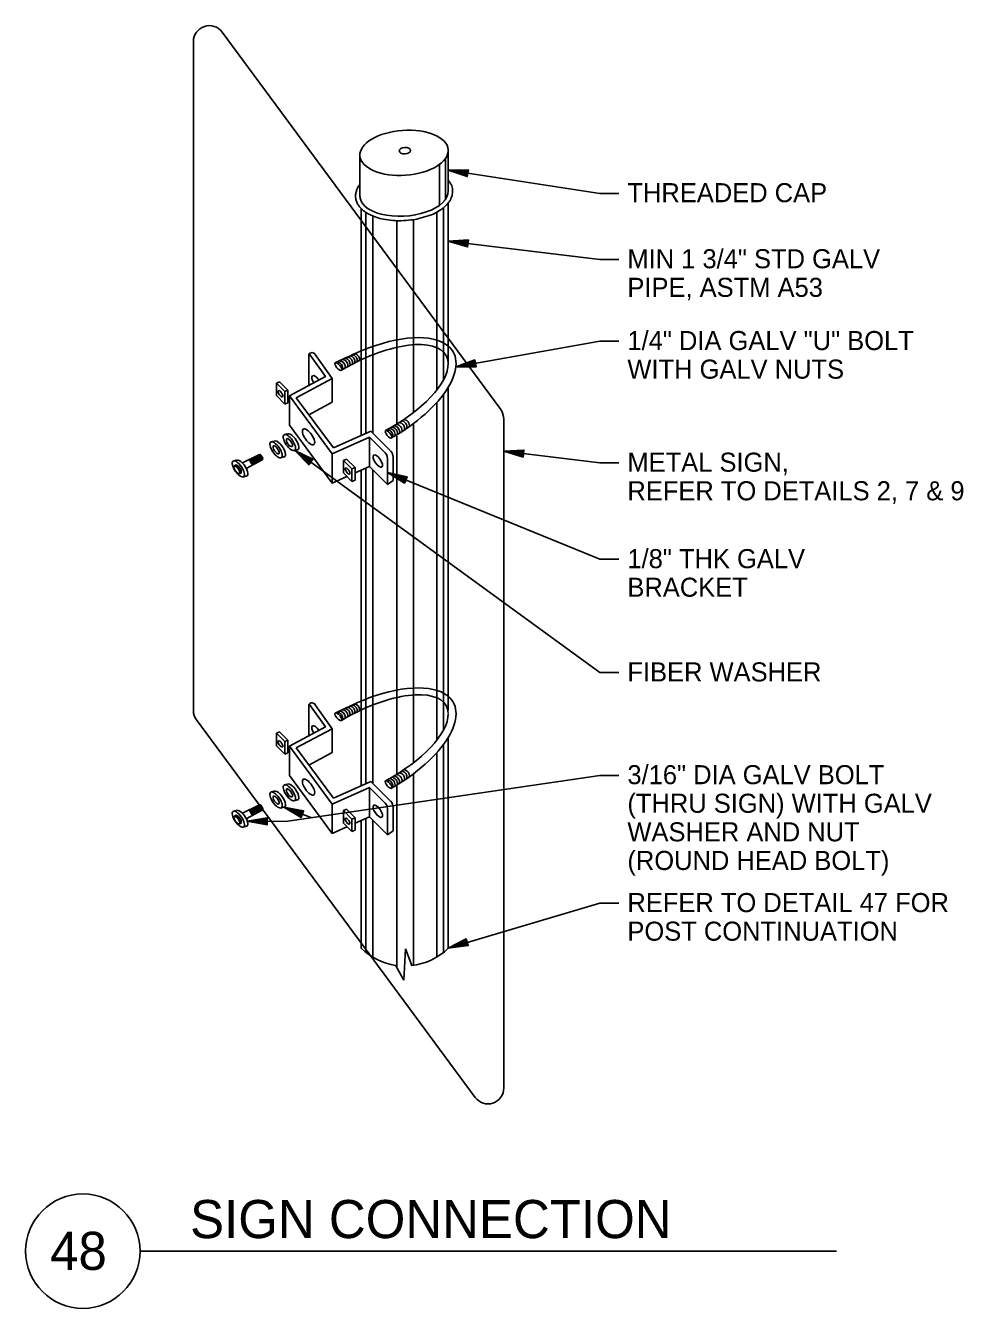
# Model space of a CAD drawing. Extents: x -121875 to -117742, y -103854 to -101122.
# Drawn here: x -120027.3 to -119732.2, y -101990.3 to -101586.5 of the extents above; entities that cross this region are included whole.
import ezdxf

# ---------------------------------------------------------------- set-up
doc = ezdxf.new("R2010")
doc.units = 0
doc.layers.add('22', color=7, linetype='Continuous')

msp = doc.modelspace()

# ---------------------------------------------------------------- linework, layer by layer
at = {"layer": '22'}
for p, q in [((-119877.8, -101707.38), (-119965.5, -101588.57)), ((-119974.52, -101591.53), (-119974.52, -101802.11)), ((-119922.11, -101640.42), (-119922.11, -101627.55)), ((-119894.32, -101638.44), (-119894.32, -101625.57)), ((-119897.12, -101643.11), (-119897.12, -101630.24)), ((-119895.14, -101641.15), (-119895.14, -101628.28)), ((-119894.32, -101693.31), (-119894.32, -101642.33)), ((-119921.71, -101715.56), (-119921.71, -101644.13)), ((-119920.23, -101714.9), (-119920.23, -101645.32)), ((-119918.08, -101714.77), (-119918.08, -101646.43)), ((-119905.21, -101708.26), (-119905.21, -101647.57)), ((-119897.95, -101701.23), (-119897.95, -101645.24)), ((-119895.8, -101698.01), (-119895.8, -101643.82)), ((-119910.49, -101711.63), (-119910.49, -101647.9)), ((-119938.2, -101689.99), (-119938.2, -101699.84)), ((-119930.86, -101697.58), (-119936.17, -101690.05)), ((-119926.19, -101690.93), (-119929.87, -101692.68)), ((-119947.43, -101698.62), (-119948.42, -101699.04)), ((-119945.79, -101701.67), (-119948.42, -101699.04)), ((-119948.42, -101699.04), (-119948.42, -101702.94)), ((-119944.8, -101701.25), (-119947.43, -101698.62)), ((-119942.15, -101703.65), (-119930.86, -101697.58)), ((-119930.86, -101697.58), (-119930.86, -101705.06)), ((-119948.42, -101702.99), (-119945.79, -101705.63)), ((-119944.8, -101701.25), (-119945.79, -101701.67)), ((-119945.79, -101705.63), (-119945.79, -101701.67)), ((-119944.8, -101705.21), (-119944.8, -101701.25)), ((-119944.27, -101703.08), (-119944.27, -101712.32)), ((-119930.48, -101719.47), (-119942.15, -101703.65)), ((-119895.8, -101808.36), (-119895.8, -101702.53)), ((-119894.32, -101802.01), (-119894.32, -101700.33)), ((-119944.8, -101705.21), (-119945.79, -101705.63)), ((-119897.95, -101811.47), (-119897.95, -101705.14)), ((-119905.21, -101818.24), (-119905.21, -101712.13)), ((-119876.83, -101920.92), (-119876.83, -101710.35)), ((-119944.98, -101715.04), (-119946.02, -101715.33)), ((-119918.66, -101714.2), (-119930.48, -101719.47)), ((-119919.13, -101716.08), (-119919.13, -101725.31)), ((-119912.44, -101720.41), (-119918.66, -101714.2)), ((-119910.49, -101822.23), (-119910.49, -101715.76)), ((-119949.17, -101717.31), (-119950.21, -101717.59)), ((-119941.59, -101719.95), (-119942.63, -101720.23)), ((-119961.04, -101723.34), (-119962.07, -101723.62)), ((-119953.93, -101721.64), (-119959.07, -101724.19)), ((-119952.9, -101723.25), (-119957.89, -101725.93)), ((-119955.63, -101724.7), (-119956.94, -101723.1)), ((-119956.94, -101723.1), (-119955.95, -101724.89)), ((-119955.35, -101724.56), (-119956.62, -101722.96)), ((-119956.62, -101722.96), (-119955.63, -101724.7)), ((-119955.01, -101724.37), (-119956.24, -101722.77)), ((-119956.24, -101722.77), (-119955.35, -101724.56)), ((-119954.68, -101724.23), (-119955.91, -101722.68)), ((-119955.91, -101722.68), (-119955.01, -101724.37)), ((-119954.4, -101724.04), (-119955.63, -101722.54)), ((-119955.63, -101722.54), (-119954.68, -101724.23)), ((-119954.07, -101723.85), (-119955.39, -101722.4)), ((-119955.39, -101722.4), (-119954.4, -101724.04)), ((-119953.69, -101723.67), (-119955.06, -101722.21)), ((-119955.06, -101722.21), (-119954.07, -101723.85)), ((-119953.32, -101723.48), (-119954.68, -101722.07)), ((-119954.68, -101722.07), (-119953.69, -101723.67)), ((-119952.99, -101723.34), (-119954.36, -101721.93)), ((-119954.36, -101721.93), (-119953.32, -101723.48)), ((-119952.7, -101723.1), (-119954.07, -101721.73)), ((-119954.07, -101721.73), (-119952.99, -101723.34)), ((-119952.7, -101722.72), (-119953.79, -101721.55)), ((-119953.79, -101721.55), (-119952.7, -101723.1)), ((-119952.65, -101722.72), (-119953.32, -101721.69)), ((-119945.79, -101722.21), (-119946.82, -101722.49)), ((-119930.81, -101721.31), (-119930.81, -101730.54)), ((-119926.29, -101722.96), (-119927.28, -101723.39)), ((-119924.64, -101726.02), (-119927.28, -101723.39)), ((-119927.28, -101723.39), (-119927.28, -101727.29)), ((-119923.65, -101725.6), (-119926.29, -101722.96)), ((-119913.48, -101723.39), (-119913.48, -101730.96)), ((-119911.68, -101722.4), (-119911.68, -101729.74)), ((-119961.56, -101725.08), (-119961.09, -101724.8)), ((-119960.8, -101725.5), (-119960.34, -101725.22)), ((-119960.01, -101726.68), (-119959.53, -101726.39)), ((-119959.96, -101727.53), (-119959.49, -101727.25)), ((-119957.65, -101728.24), (-119958.69, -101728.52)), ((-119927.28, -101727.34), (-119924.64, -101729.97)), ((-119923.65, -101725.6), (-119924.64, -101726.02)), ((-119924.64, -101729.97), (-119924.64, -101726.02)), ((-119923.65, -101729.55), (-119923.65, -101725.6)), ((-119921.71, -101825.75), (-119921.71, -101726.42)), ((-119920.23, -101825.14), (-119920.23, -101726.01)), ((-119918.08, -101825.01), (-119918.08, -101726.3)), ((-119923.65, -101729.55), (-119924.64, -101729.97)), ((-119913.48, -101730.96), (-119911.68, -101729.74)), ((-119938.2, -101800.23), (-119938.2, -101810.08)), ((-119930.86, -101807.82), (-119936.17, -101800.29)), ((-119926.19, -101801.17), (-119929.87, -101802.92)), ((-119973.55, -101805.08), (-119885.85, -101923.89)), ((-119947.43, -101808.86), (-119948.42, -101809.28)), ((-119945.79, -101811.91), (-119948.42, -101809.28)), ((-119948.42, -101809.28), (-119948.42, -101813.18)), ((-119944.8, -101811.49), (-119947.43, -101808.86)), ((-119942.15, -101813.89), (-119930.86, -101807.82)), ((-119930.86, -101807.82), (-119930.86, -101815.3)), ((-119948.42, -101813.23), (-119945.79, -101815.87)), ((-119944.8, -101811.49), (-119945.79, -101811.91)), ((-119945.79, -101815.87), (-119945.79, -101811.91)), ((-119944.8, -101815.44), (-119944.8, -101811.49)), ((-119895.8, -101878.23), (-119895.8, -101812.77)), ((-119894.32, -101876.91), (-119894.32, -101810.57)), ((-119944.8, -101815.44), (-119945.79, -101815.87)), ((-119944.27, -101813.32), (-119944.27, -101822.55)), ((-119930.48, -101829.71), (-119942.15, -101813.89)), ((-119897.95, -101879.73), (-119897.95, -101815.38)), ((-119944.98, -101825.28), (-119946.02, -101825.57)), ((-119918.66, -101824.44), (-119930.48, -101829.71)), ((-119912.44, -101830.65), (-119918.66, -101824.44)), ((-119905.21, -101882.32), (-119905.21, -101821.95)), ((-119949.17, -101827.54), (-119950.21, -101827.83)), ((-119919.13, -101826.32), (-119919.13, -101835.55)), ((-119910.49, -101883.04), (-119910.49, -101825.5)), ((-119953.93, -101831.88), (-119959.07, -101834.42)), ((-119952.9, -101833.49), (-119957.89, -101836.17)), ((-119955.63, -101834.94), (-119956.94, -101833.34)), ((-119956.94, -101833.34), (-119955.95, -101835.13)), ((-119955.35, -101834.8), (-119956.62, -101833.2)), ((-119956.62, -101833.2), (-119955.63, -101834.94)), ((-119955.01, -101834.61), (-119956.24, -101833.01)), ((-119956.24, -101833.01), (-119955.35, -101834.8)), ((-119954.68, -101834.47), (-119955.91, -101832.92)), ((-119955.91, -101832.92), (-119955.01, -101834.61)), ((-119954.4, -101834.28), (-119955.63, -101832.78)), ((-119955.63, -101832.78), (-119954.68, -101834.47)), ((-119954.07, -101834.09), (-119955.39, -101832.64)), ((-119955.39, -101832.64), (-119954.4, -101834.28)), ((-119953.69, -101833.91), (-119955.06, -101832.45)), ((-119955.06, -101832.45), (-119954.07, -101834.09)), ((-119953.32, -101833.72), (-119954.68, -101832.3)), ((-119954.68, -101832.3), (-119953.69, -101833.91)), ((-119952.99, -101833.58), (-119954.36, -101832.17)), ((-119954.36, -101832.17), (-119953.32, -101833.72)), ((-119952.7, -101833.34), (-119954.07, -101831.97)), ((-119954.07, -101831.97), (-119952.99, -101833.58)), ((-119952.7, -101832.96), (-119953.79, -101831.79)), ((-119953.79, -101831.79), (-119952.7, -101833.34)), ((-119952.65, -101832.96), (-119953.32, -101831.93)), ((-119945.79, -101832.45), (-119946.82, -101832.73)), ((-119941.59, -101830.18), (-119942.63, -101830.47)), ((-119930.81, -101831.55), (-119930.81, -101840.78)), ((-119926.29, -101833.2), (-119927.28, -101833.63)), ((-119923.65, -101835.84), (-119926.29, -101833.2)), ((-119911.68, -101832.64), (-119911.68, -101839.98)), ((-119961.04, -101833.58), (-119962.07, -101833.86)), ((-119961.56, -101835.32), (-119961.09, -101835.04)), ((-119960.8, -101835.74), (-119960.34, -101835.46)), ((-119960.01, -101836.92), (-119959.53, -101836.63)), ((-119959.96, -101837.77), (-119959.49, -101837.49)), ((-119924.64, -101836.26), (-119927.28, -101833.63)), ((-119927.28, -101833.63), (-119927.28, -101837.53)), ((-119923.65, -101835.84), (-119924.64, -101836.26)), ((-119924.64, -101840.21), (-119924.64, -101836.26)), ((-119923.65, -101839.79), (-119923.65, -101835.84)), ((-119921.71, -101876.91), (-119921.71, -101836.71)), ((-119920.23, -101878.23), (-119920.23, -101836.05)), ((-119918.08, -101879.73), (-119918.08, -101836.6)), ((-119913.48, -101833.63), (-119913.48, -101841.2)), ((-119957.65, -101838.48), (-119958.69, -101838.76)), ((-119927.28, -101837.58), (-119924.64, -101840.21)), ((-119923.65, -101839.79), (-119924.64, -101840.21)), ((-119913.48, -101841.2), (-119911.68, -101839.98)), ((-119907.76, -101877.08), (-119908.25, -101886.98)), ((-119905.79, -101882.4), (-119907.76, -101877.08)), ((-119908.25, -101886.98), (-119910.91, -101882.31)), ((-119772.06, -101972.28), (-119991.33, -101972.28))]:
    msp.add_line(p, q, dxfattribs=at)
for points in [[(-119887.97, -101631.87), (-119888.31, -101634.04), (-119894.32, -101632), (-119887.97, -101631.87), (-119888.44, -101632.91), (-119888.46, -101633.71), (-119892.98, -101632.16), (-119888.2, -101632.04), (-119888.64, -101632.88), (-119888.71, -101633.37), (-119891.84, -101632.33), (-119888.64, -101632.27), (-119888.84, -101633.2), (-119890.71, -101632.56), (-119888.89, -101632.54), (-119889.1, -101632.96), (-119889.72, -101632.71), (-119888.14, -101632.96)], [(-119840.59, -101639.32), (-119846.59, -101639.32), (-119894.32, -101632)], [(-119887.98, -101653.99), (-119888.25, -101656.17), (-119894.32, -101654.33), (-119887.98, -101653.99), (-119888.41, -101655.04), (-119888.41, -101655.85), (-119892.97, -101654.44), (-119888.2, -101654.16), (-119888.61, -101655.02), (-119888.67, -101655.51), (-119891.83, -101654.58), (-119888.64, -101654.41), (-119888.8, -101655.35), (-119890.7, -101654.76), (-119888.87, -101654.68), (-119889.07, -101655.11), (-119889.7, -101654.88), (-119888.11, -101655.08)], [(-119840.59, -101660.12), (-119846.59, -101660.12), (-119894.32, -101654.33)], [(-119840.59, -101685.86), (-119846.59, -101685.86), (-119891.91, -101693.94)], [(-119914.19, -101721.03), (-119919.13, -101716.08), (-119930.81, -101721.31), (-119944.27, -101703.08), (-119932.98, -101697.01), (-119937.97, -101689.99)], [(-119885.95, -101691.77), (-119885.57, -101693.94), (-119891.91, -101693.94), (-119885.95, -101691.77), (-119886.05, -101692.91), (-119885.82, -101693.68), (-119890.59, -101693.65), (-119886.11, -101692), (-119886.25, -101692.94), (-119886.16, -101693.43), (-119889.46, -101693.45), (-119886.45, -101692.37), (-119886.34, -101693.31), (-119888.32, -101693.31), (-119886.6, -101692.7), (-119886.67, -101693.17), (-119887.33, -101693.13), (-119885.76, -101692.86)], [(-119938.15, -101709.07), (-119930.86, -101705.06)], [(-119926.19, -101728.47), (-119930.81, -101730.54), (-119944.27, -101712.32)], [(-119840.59, -101790.16), (-119846.59, -101790.16), (-119942.64, -101720.23)], [(-119936.93, -101723), (-119938.22, -101724.78), (-119942.64, -101720.23), (-119936.93, -101723), (-119937.81, -101723.71), (-119938.2, -101724.42), (-119941.51, -101720.98), (-119937.21, -101723.04), (-119937.98, -101723.59), (-119938.27, -101724), (-119940.58, -101721.65), (-119937.71, -101723.05), (-119938.3, -101723.79), (-119939.68, -101722.36), (-119938.04, -101723.18), (-119938.43, -101723.45), (-119938.87, -101722.95), (-119937.57, -101723.89)], [(-119870.49, -101720.14), (-119870.75, -101722.32), (-119876.83, -101720.48), (-119870.49, -101720.14), (-119870.92, -101721.19), (-119870.92, -101722), (-119875.48, -101720.59), (-119870.71, -101720.31), (-119871.12, -101721.17), (-119871.18, -101721.67), (-119874.34, -101720.73), (-119871.14, -101720.56), (-119871.31, -101721.5), (-119873.2, -101720.92), (-119871.38, -101720.84), (-119871.58, -101721.27), (-119872.21, -101721.04), (-119870.62, -101721.23)], [(-119840.59, -101724.15), (-119846.59, -101724.15), (-119876.83, -101720.48)], [(-119960.24, -101726.25), (-119960.8, -101725.5), (-119961.56, -101725.08), (-119961.84, -101725.55), (-119961.47, -101726.44), (-119961, -101727.06), (-119960.48, -101727.53), (-119959.96, -101727.53), (-119960.01, -101726.68), (-119960.29, -101726.21)], [(-119959.77, -101725.97), (-119960.34, -101725.22), (-119961.09, -101724.8), (-119961.09, -101724.84)], [(-119959.53, -101727.25), (-119959.49, -101727.25), (-119959.53, -101726.39), (-119959.81, -101725.93)], [(-119913.48, -101730.96), (-119919.13, -101725.31), (-119923.65, -101727.34)], [(-119840.59, -101754.51), (-119846.59, -101754.51), (-119913.48, -101727.17)], [(-119907.27, -101728.5), (-119908.1, -101730.54), (-119913.48, -101727.17), (-119907.27, -101728.5), (-119907.96, -101729.4), (-119908.17, -101730.18), (-119912.21, -101727.63), (-119907.53, -101728.61), (-119908.15, -101729.33), (-119908.34, -101729.79), (-119911.14, -101728.06), (-119908.02, -101728.74), (-119908.42, -101729.6), (-119910.1, -101728.54), (-119908.31, -101728.94), (-119908.62, -101729.3), (-119909.17, -101728.92), (-119907.69, -101729.52)], [(-119914.19, -101831.27), (-119919.13, -101826.32), (-119930.81, -101831.55), (-119944.27, -101813.32), (-119932.98, -101807.25), (-119937.97, -101800.23)], [(-119938.15, -101819.31), (-119930.86, -101815.3)], [(-119840.59, -101822.51), (-119846.59, -101822.51), (-119945.59, -101837.08)], [(-119926.19, -101838.71), (-119930.81, -101840.78), (-119944.27, -101822.55)], [(-119937.21, -101835.84), (-119946.09, -101832.54)], [(-119939.85, -101833.66), (-119940.61, -101835.73), (-119946.09, -101832.54), (-119939.85, -101833.66), (-119940.51, -101834.59), (-119940.69, -101835.38), (-119944.81, -101832.95), (-119940.11, -101833.78), (-119940.7, -101834.52), (-119940.87, -101834.99), (-119943.73, -101833.35), (-119940.58, -101833.93), (-119940.96, -101834.8), (-119942.67, -101833.8), (-119940.88, -101834.14), (-119941.17, -101834.51), (-119941.73, -101834.14), (-119940.23, -101834.7)], [(-119960.24, -101836.49), (-119960.8, -101835.74), (-119961.56, -101835.32), (-119961.84, -101835.79), (-119961.47, -101836.68), (-119961, -101837.3), (-119960.48, -101837.77), (-119959.96, -101837.77), (-119960.01, -101836.92), (-119960.29, -101836.45)], [(-119959.77, -101836.21), (-119960.34, -101835.46), (-119961.09, -101835.04), (-119961.09, -101835.08)], [(-119959.53, -101837.49), (-119959.49, -101837.49), (-119959.53, -101836.63), (-119959.81, -101836.17)], [(-119951.3, -101835.9), (-119951.32, -101838.1), (-119957.56, -101836.94), (-119951.3, -101835.9), (-119951.61, -101837), (-119951.51, -101837.8), (-119956.2, -101836.9), (-119951.5, -101836.1), (-119951.81, -101837), (-119951.81, -101837.5), (-119955.05, -101836.91), (-119951.9, -101836.4), (-119951.96, -101837.35), (-119953.91, -101836.98), (-119952.1, -101836.69), (-119952.26, -101837.14), (-119952.91, -101836.98), (-119951.31, -101837)], [(-119945.59, -101837.08), (-119957.56, -101836.94)], [(-119913.48, -101841.2), (-119919.13, -101835.55), (-119923.65, -101837.58)], [(-119840.59, -101862.78), (-119846.59, -101862.78), (-119894.32, -101876.91)], [(-119888.68, -101874.01), (-119888.02, -101876.11), (-119894.32, -101876.91), (-119888.68, -101874.01), (-119888.64, -101875.14), (-119888.3, -101875.88), (-119893.04, -101876.46), (-119888.81, -101874.26), (-119888.83, -101875.2), (-119888.68, -101875.68), (-119891.95, -101876.12), (-119889.1, -101874.66), (-119888.87, -101875.58), (-119890.83, -101875.83), (-119889.2, -101875.01), (-119889.21, -101875.48), (-119889.88, -101875.53), (-119888.35, -101875.06)]]:
    msp.add_lwpolyline(points, dxfattribs=at)
msp.add_circle((-120009.33, -101972.28), 18, dxfattribs=at)
for centre, radius, start, end in [((-119969.52, -101591.53), 5, 36.4317, 180), ((-119937.2, -101690.66), 1.2, 30.9874, 146.3482), ((-119938.06, -101690.16), 0.217, 77.4712, 130.6013), ((-119928.68, -101693.94), 1.92, 348.2285, 85.9146), ((-119927.83, -101693.52), 1.92, 348.2285, 85.9146), ((-119927.16, -101693.16), 1.98, 353.3183, 77.9923), ((-119926.41, -101692.78), 1.98, 353.3183, 77.9923), ((-119925.66, -101692.36), 1.98, 353.3183, 77.9923), ((-119924.9, -101692.03), 1.98, 353.3183, 77.9923), ((-119924.2, -101691.7), 1.98, 353.3183, 77.9923), ((-119929.43, -101694.32), 1.92, 348.2285, 85.9146), ((-119881.83, -101710.35), 5, 0, 36.4317), ((-119910.78, -101713.95), 1.92, 348.2285, 85.9146), ((-119909.98, -101713.39), 1.92, 348.2285, 85.9146), ((-119909.23, -101712.87), 1.92, 348.2285, 85.9146), ((-119908.48, -101712.4), 1.92, 348.2285, 85.9146), ((-119913.66, -101715.65), 1.92, 348.2285, 85.9146), ((-119912.95, -101715.23), 1.92, 348.2285, 85.9146), ((-119912.24, -101714.8), 1.92, 348.2285, 85.9146), ((-119911.58, -101714.38), 1.92, 348.2285, 85.9146), ((-119914.26, -101722.25), 2.58, 356.6267, 44.9178), ((-119953.67, -101722.1), 0.549, 50.7562, 120.4157), ((-119953.03, -101722.87), 0.402, 290.556, 20.556), ((-119916, -101722.86), 2.58, 348.5235, 44.9178), ((-119937.2, -101800.9), 1.2, 30.9874, 146.3482), ((-119938.06, -101800.4), 0.217, 77.4712, 130.6013), ((-119926.41, -101803.02), 1.98, 353.3183, 77.9923), ((-119925.66, -101802.6), 1.98, 353.3183, 77.9923), ((-119924.9, -101802.27), 1.98, 353.3183, 77.9923), ((-119924.2, -101801.94), 1.98, 353.3183, 77.9923), ((-119969.52, -101802.11), 5, 180, 216.4317), ((-119929.43, -101804.56), 1.92, 348.2285, 85.9146), ((-119928.68, -101804.18), 1.92, 348.2285, 85.9146), ((-119927.83, -101803.76), 1.92, 348.2285, 85.9146), ((-119927.16, -101803.4), 1.98, 353.3183, 77.9923), ((-119909.23, -101823.11), 1.92, 348.2285, 85.9146), ((-119908.48, -101822.64), 1.92, 348.2285, 85.9146), ((-119913.66, -101825.89), 1.92, 348.2285, 85.9146), ((-119912.95, -101825.47), 1.92, 348.2285, 85.9146), ((-119912.24, -101825.04), 1.92, 348.2285, 85.9146), ((-119911.58, -101824.62), 1.92, 348.2285, 85.9146), ((-119910.78, -101824.19), 1.92, 348.2285, 85.9146), ((-119909.98, -101823.63), 1.92, 348.2285, 85.9146), ((-119953.67, -101832.34), 0.549, 50.7562, 120.4157), ((-119953.03, -101833.11), 0.402, 290.556, 20.556), ((-119916, -101833.1), 2.58, 348.5235, 44.9178), ((-119914.26, -101832.49), 2.58, 356.6267, 44.9178), ((-119908.02, -101863), 19.52, 225.4381, 261.6907), ((-119908.02, -101863), 19.52, 276.1221, 314.5619), ((-119881.83, -101920.92), 5, 216.4317, 0)]:
    msp.add_arc(centre, radius, start, end, dxfattribs=at)
for centre, major_axis, ratio in [((-119908.22, -101626.56), (-13.9, -0.99), 0.50721), ((-119907.96, -101625.88), (-1.77, -0.06), 0.577116), ((-119928.9, -101693.84), (-0.97, 1.15), 0.383233), ((-119928.9, -101693.84), (-0.97, 1.15), 0.383233), ((-119947.14, -101702.38), (0.646, -0.94), 0.40079), ((-119944.32, -101717.78), (1.68, -2.44), 0.40079), ((-119944.32, -101717.78), (0.84, -1.22), 0.40079), ((-119938.29, -101715.95), (1.68, -2.44), 0.40079), ((-119913.12, -101715.17), (-0.97, 1.15), 0.383233), ((-119948.51, -101720.04), (1.68, -2.44), 0.40079), ((-119948.51, -101720.04), (0.84, -1.22), 0.40079), ((-119960.38, -101726.07), (1.68, -2.44), 0.40079), ((-119916.49, -101723.58), (1.29, -1.88), 0.40079), ((-119926, -101726.73), (0.646, -0.94), 0.40079), ((-119928.9, -101804.08), (-0.97, 1.15), 0.383233), ((-119928.9, -101804.08), (-0.97, 1.15), 0.383233), ((-119947.14, -101812.62), (0.646, -0.94), 0.40079), ((-119944.32, -101828.02), (1.68, -2.44), 0.40079), ((-119938.29, -101826.19), (1.68, -2.44), 0.40079), ((-119913.12, -101825.41), (-0.97, 1.15), 0.383233), ((-119948.51, -101830.28), (1.68, -2.44), 0.40079), ((-119948.51, -101830.28), (0.84, -1.22), 0.40079), ((-119944.32, -101828.02), (0.84, -1.22), 0.40079), ((-119960.38, -101836.31), (1.68, -2.44), 0.40079), ((-119916.49, -101833.82), (1.29, -1.88), 0.40079), ((-119926, -101836.97), (0.646, -0.94), 0.40079)]:
    msp.add_ellipse(centre, major_axis=major_axis, ratio=ratio, dxfattribs=at)
for centre, major_axis, ratio, start_param, end_param in [((-119908.22, -101639.43), (-13.9, -0.99), 0.50721, 6.210939, 9.409079), ((-119920.84, -101704.53), (-28.17, -15.1), 0.453878, 3.333026, 4.493389), ((-119919.57, -101703.68), (-24.64, -13.25), 0.417549, 2.948396, 4.572315), ((-119920.84, -101704.53), (-28.17, -15.1), 0.453878, 1.635731, 3.31856), ((-119919.57, -101703.68), (-24.64, -13.25), 0.417549, 4.576463, 4.828697), ((-119920.84, -101704.53), (-28.17, -15.1), 0.453878, 4.503849, 4.659634), ((-119919.57, -101703.68), (-24.64, -13.25), 0.417549, 1.568045, 2.928691), ((-119935.75, -101698.62), (1.29, -1.88), 0.40079, 1.582571, 4.626709), ((-119943.28, -101717.5), (1.68, -2.44), 0.40079, 6.029102, 9.372684), ((-119947.47, -101719.76), (1.68, -2.44), 0.40079, 6.029102, 9.372684), ((-119959.34, -101725.79), (1.68, -2.44), 0.40079, 6.029102, 9.372684), ((-119919.57, -101813.92), (-24.64, -13.25), 0.417549, 2.948396, 4.572315), ((-119920.84, -101814.77), (-28.17, -15.1), 0.453878, 3.333026, 4.493389), ((-119920.84, -101814.77), (-28.17, -15.1), 0.453878, 4.503849, 4.659634), ((-119920.84, -101814.77), (-28.17, -15.1), 0.453878, 1.635731, 3.31856), ((-119919.57, -101813.92), (-24.64, -13.25), 0.417549, 4.576463, 4.828697), ((-119919.57, -101813.92), (-24.64, -13.25), 0.417549, 1.568045, 2.928691), ((-119935.75, -101808.86), (1.29, -1.88), 0.40079, 1.582571, 4.626709), ((-119943.28, -101827.74), (1.68, -2.44), 0.40079, 6.029102, 9.372684), ((-119947.47, -101830), (1.68, -2.44), 0.40079, 6.029102, 9.372684), ((-119959.34, -101836.03), (1.68, -2.44), 0.40079, 6.029102, 9.372684)]:
    msp.add_ellipse(centre, major_axis=major_axis, ratio=ratio, start_param=start_param, end_param=end_param, dxfattribs=at)
for points in [[(-119894.32, -101635.17), (-119893.97, -101635.58), (-119893.68, -101636.02), (-119893.18, -101637.07), (-119893, -101637.7), (-119892.91, -101638.99), (-119892.99, -101639.63), (-119893.38, -101640.86), (-119893.68, -101641.45), (-119894.46, -101642.55), (-119894.93, -101643.06), (-119896.02, -101644.02), (-119896.64, -101644.47), (-119898.71, -101645.71), (-119900.32, -101646.38), (-119903.8, -101647.37), (-119905.68, -101647.7), (-119909.55, -101647.98), (-119911.46, -101647.92), (-119915.05, -101647.43), (-119916.73, -101647), (-119918.96, -101646.06), (-119919.64, -101645.7), (-119920.86, -101644.91), (-119921.4, -101644.47), (-119922.32, -101643.49), (-119922.7, -101642.95), (-119923.26, -101641.79), (-119923.43, -101641.16), (-119923.48, -101640.52)], [(-119923.48, -101640.52), (-119923.52, -101639.87), (-119923.44, -101639.23), (-119923.05, -101637.99), (-119922.75, -101637.41), (-119922.28, -101636.75), (-119922.2, -101636.64), (-119922.11, -101636.53)]]:
    msp.add_open_spline(points, degree=3, dxfattribs=at)

# ---------------------------------------------------------------- texts
for s, height, p in [('THREADED CAP', 6, (-119837.92, -101642.11)), ('MIN 1 3/4" STD GALV', 6, (-119837.92, -101662.9)), ('PIPE, ASTM A53', 6, (-119837.92, -101671.9)), ('1/4" DIA GALV "U" BOLT', 6, (-119837.92, -101688.65)), ('WITH GALV NUTS', 6, (-119837.92, -101697.65)), ('METAL SIGN,', 6, (-119837.92, -101726.94)), ('REFER TO DETAILS 2, 7 & 9', 6, (-119837.92, -101735.94)), ('1/8" THK GALV', 6, (-119837.92, -101757.3)), ('BRACKET', 6, (-119837.92, -101766.3)), ('FIBER WASHER', 6, (-119837.92, -101792.95)), ('3/16" DIA GALV BOLT', 6, (-119837.92, -101825.3)), ('(THRU SIGN) WITH GALV', 6, (-119837.92, -101834.3)), ('WASHER AND NUT', 6, (-119837.92, -101843.3)), ('(ROUND HEAD BOLT)', 6, (-119837.92, -101852.3)), ('REFER TO DETAIL 47 FOR', 6, (-119837.92, -101865.56)), ('POST CONTINUATION', 6, (-119837.92, -101874.56)), ('SIGN CONNECTION', 12, (-119975.58, -101968.18)), ('48', 12, (-120019.63, -101978.18))]:
    msp.add_text(s, height=height, dxfattribs=at).set_placement(p)

doc.saveas('drawing.dxf')
